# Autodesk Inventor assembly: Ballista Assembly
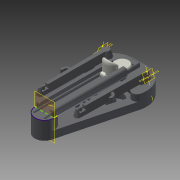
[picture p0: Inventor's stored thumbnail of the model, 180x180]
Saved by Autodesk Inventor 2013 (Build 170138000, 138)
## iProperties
Created: 2013-06
Part Number: Ballista Assembly
Document SubType Name: Assembly
Designer: merrill
Mass: 75.541 g
Surface Area: 381.12 cm^2
Volume: 75.1512 cm^3
Density: 1.00519 g/cm^3
Author: merrill
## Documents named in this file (5)
- C:\Users\merrill\Documents\Autodesk\Projects\Ballista Assembly.iam
- C:\Users\merrill\Documents\Autodesk\Projects\Ballista Base.ipt
- C:\Users\merrill\Documents\Autodesk\Projects\Ballista Arm Double Size.ipt
- C:\Users\merrill\Documents\Autodesk\Projects\Ballista Arm Double Size Mirrored.ipt
- C:\Users\merrill\Documents\Autodesk\Projects\Ballista Sling.ipt
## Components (4 placed, 4 different names)
1. Ballista Base:1 — Angle:1, Insert:1, Insert:2, Mate:1, Mate:2
2. Ballista Arm Double Size:1 — Rotation:1, Insert:2
3. Ballista Arm Double Size Mirrored:1 — Rotation:1, Insert:1
4. Ballista Sling:1 — Mate:1, Mate:2
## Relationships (6: Insert 2, Mate 2, Angle 1, RelateRotation 1)
- Angle:1: Ballista Base:1
- Rotation:1 [RelateRotation]: Ballista Arm Double Size:1 ↔ Ballista Arm Double Size Mirrored:1
- Insert:1: Ballista Base:1 ↔ Ballista Arm Double Size Mirrored:1
- Insert:2: Ballista Base:1 ↔ Ballista Arm Double Size:1
- Mate:1: Ballista Base:1 ↔ Ballista Sling:1
- Mate:2: Ballista Base:1 ↔ Ballista Sling:1
